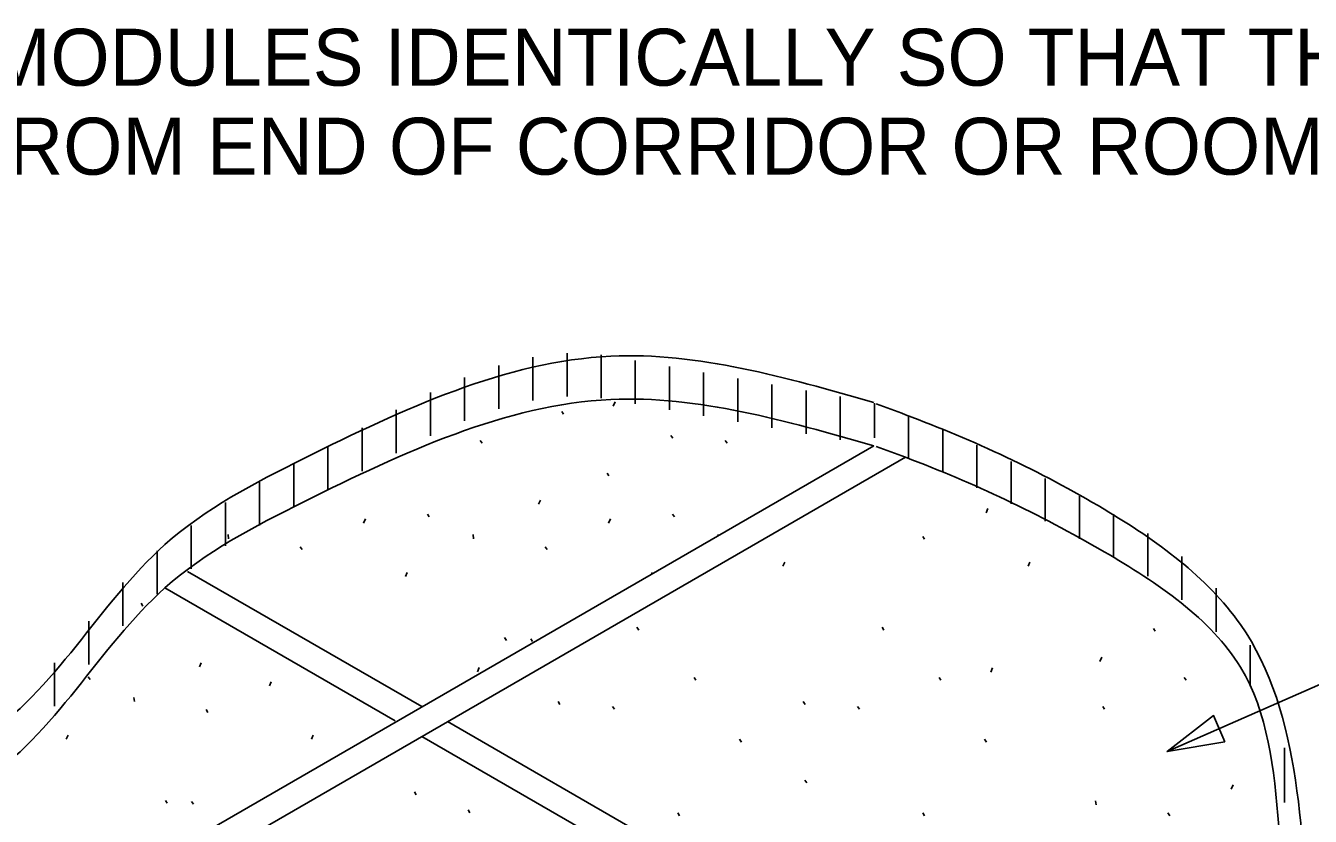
# Model space of a CAD drawing. Extents: x -12092.5 to -12048.3, y -12283.2 to -12205.8.
# Drawn here: x -12075.14 to -12060.1, y -12253.65 to -12244.4 of the extents above; entities that cross this region are included whole.
import ezdxf

# ---------------------------------------------------------------- set-up
doc = ezdxf.new("R2010")
doc.units = 0
for name, color, linetype in [('G-ANNO-TEXT', 7, 'Continuous'), ('G-DETL-LINE', 7, 'Continuous'), ('G-DETL-PATT', 7, 'Continuous')]:
    doc.layers.add(name, color=color, linetype=linetype)

msp = doc.modelspace()

# ---------------------------------------------------------------- linework, layer by layer
at = {"layer": 'G-ANNO-TEXT'}
msp.add_line((-12056.825041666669, -12250.714299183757), (-12061.776083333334, -12252.892184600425), dxfattribs=at)
msp.add_lwpolyline([(-12061.098739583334, -12252.776312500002), (-12061.776083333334, -12252.892187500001), (-12061.232958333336, -12252.471197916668)], close=True, dxfattribs=at)
at = {"layer": 'G-DETL-LINE'}
for p, q in [((-12065.209760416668, -12249.312927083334), (-12087.406947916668, -12262.1285)), ((-12064.841333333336, -12249.446656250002), (-12087.432489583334, -12262.489625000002)), ((-12073.246770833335, -12250.782447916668), (-12070.504281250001, -12252.365822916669)), ((-12070.813479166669, -12252.533729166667), (-12073.510177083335, -12250.976802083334)), ((-12070.200906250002, -12252.541000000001), (-12062.680635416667, -12256.882791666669)), ((-12062.980645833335, -12257.056000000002), (-12070.500906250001, -12252.714197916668))]:
    msp.add_line(p, q, dxfattribs=at)
for points in [[(-12065.209760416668, -12248.805854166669), (-12068.289083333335, -12248.263375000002), (-12071.882447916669, -12249.459791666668), (-12073.510843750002, -12250.469312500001), (-12075.660083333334, -12252.742270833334), (-12078.577770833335, -12254.06140625), (-12080.241072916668, -12256.115031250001), (-12082.416833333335, -12256.791677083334), (-12085.365218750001, -12258.540291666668), (-12087.392239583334, -12261.546677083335), (-12087.416020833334, -12262.222104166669)], [(-12065.209760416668, -12249.312927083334), (-12068.289083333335, -12248.770458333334), (-12071.882447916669, -12249.966864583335), (-12073.510843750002, -12250.976395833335), (-12075.660083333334, -12253.249343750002), (-12078.577770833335, -12254.568479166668), (-12080.241072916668, -12256.622104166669), (-12082.416833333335, -12257.298750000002), (-12085.365218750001, -12259.047364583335), (-12087.392239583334, -12262.053750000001), (-12087.392239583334, -12263.004739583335), (-12085.887333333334, -12270.45934375), (-12085.273083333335, -12271.195604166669), (-12082.387489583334, -12274.137000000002), (-12077.473510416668, -12274.658520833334), (-12076.367854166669, -12274.658520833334), (-12074.064416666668, -12273.584802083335), (-12070.747468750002, -12271.314677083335), (-12067.092677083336, -12270.27165625), (-12063.192208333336, -12269.382020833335), (-12061.824302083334, -12266.020250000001), (-12056.450385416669, -12263.782125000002), (-12054.537635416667, -12261.234708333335), (-12060.101572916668, -12255.740187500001), (-12060.917697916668, -12251.902302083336), (-12062.514739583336, -12250.552489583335), (-12064.841333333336, -12249.446656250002), (-12065.182322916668, -12249.321343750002)], [(-12060.101218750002, -12255.246270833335), (-12060.101572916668, -12255.24159375), (-12060.917697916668, -12251.403708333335), (-12062.514739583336, -12250.053895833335), (-12064.841333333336, -12248.948052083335), (-12065.182322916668, -12248.822739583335)]]:
    msp.add_spline(points, degree=3, dxfattribs=at)
at = {"layer": 'G-DETL-PATT'}
for p, q in [((-12069.202864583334, -12248.781031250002), (-12069.202864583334, -12248.273958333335)), ((-12068.802864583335, -12248.736291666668), (-12068.802864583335, -12248.229218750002)), ((-12068.402864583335, -12248.753270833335), (-12068.402864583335, -12248.2461875)), ((-12068.002864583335, -12248.820875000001), (-12068.002864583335, -12248.313802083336)), ((-12069.602864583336, -12248.879083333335), (-12069.602864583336, -12248.372000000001)), ((-12067.602864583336, -12248.891343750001), (-12067.602864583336, -12248.384270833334)), ((-12067.202864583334, -12248.961802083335), (-12067.202864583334, -12248.454729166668)), ((-12070.002864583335, -12249.021187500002), (-12070.002864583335, -12248.514114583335)), ((-12066.802864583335, -12249.032281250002), (-12066.802864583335, -12248.525208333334)), ((-12066.402864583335, -12249.102739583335), (-12066.402864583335, -12248.595666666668)), ((-12070.402864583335, -12249.197427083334), (-12070.402864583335, -12248.690354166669)), ((-12066.002864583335, -12249.173208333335), (-12066.002864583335, -12248.666125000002)), ((-12065.602864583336, -12249.243677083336), (-12065.602864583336, -12248.736604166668)), ((-12070.802864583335, -12249.397250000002), (-12070.802864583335, -12248.890177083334)), ((-12068.865145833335, -12248.909625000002), (-12068.843583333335, -12248.941989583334)), ((-12068.261354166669, -12248.846593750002), (-12068.239760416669, -12248.798031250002)), ((-12065.202864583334, -12249.22071875), (-12065.202864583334, -12248.815354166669)), ((-12064.802864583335, -12249.461541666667), (-12064.802864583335, -12248.962937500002)), ((-12071.202864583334, -12249.609614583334), (-12071.202864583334, -12249.102541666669)), ((-12067.586989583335, -12249.191812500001), (-12067.565427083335, -12249.224218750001)), ((-12064.402864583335, -12249.625041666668), (-12064.402864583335, -12249.126437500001)), ((-12071.602864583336, -12249.823114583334), (-12071.602864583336, -12249.316041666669)), ((-12069.819260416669, -12249.250208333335), (-12069.79765625, -12249.282604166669)), ((-12066.949458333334, -12249.250208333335), (-12066.927854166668, -12249.282604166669)), ((-12064.002864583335, -12249.803104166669), (-12064.002864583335, -12249.304500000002)), ((-12063.602864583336, -12249.993531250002), (-12063.602864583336, -12249.494927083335)), ((-12072.002864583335, -12250.027989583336), (-12072.002864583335, -12249.520916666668)), ((-12068.333020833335, -12249.633343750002), (-12068.311416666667, -12249.665708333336)), ((-12072.402864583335, -12250.244583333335), (-12072.402864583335, -12249.737500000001)), ((-12063.202864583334, -12250.19371875), (-12063.202864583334, -12249.695114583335)), ((-12069.135260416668, -12249.995625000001), (-12069.113697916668, -12249.947104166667)), ((-12062.802864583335, -12250.400791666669), (-12062.802864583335, -12249.902187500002)), ((-12072.802864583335, -12250.484687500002), (-12072.802864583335, -12249.977614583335)), ((-12070.436541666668, -12250.112291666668), (-12070.414979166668, -12250.144687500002)), ((-12067.566739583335, -12250.112291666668), (-12067.545177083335, -12250.144687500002)), ((-12063.895531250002, -12250.096000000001), (-12063.873927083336, -12250.047479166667)), ((-12062.402864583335, -12250.612093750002), (-12062.402864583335, -12250.113343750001)), ((-12073.202864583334, -12250.751437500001), (-12073.202864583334, -12250.244364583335)), ((-12071.185083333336, -12250.216843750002), (-12071.163479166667, -12250.168312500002)), ((-12068.315281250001, -12250.216843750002), (-12068.293677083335, -12250.168312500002)), ((-12072.772270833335, -12250.352333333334), (-12072.766864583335, -12250.400895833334)), ((-12069.902468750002, -12250.352333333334), (-12069.897072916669, -12250.400895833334)), ((-12067.032666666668, -12250.352333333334), (-12067.031302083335, -12250.364604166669)), ((-12064.636979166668, -12250.37459375), (-12064.615416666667, -12250.406958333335)), ((-12062.002864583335, -12250.839770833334), (-12062.002864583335, -12250.338281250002)), ((-12073.602864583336, -12251.048687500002), (-12073.602864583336, -12250.541614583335)), ((-12071.926531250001, -12250.495427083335), (-12071.904968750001, -12250.52779166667)), ((-12069.056729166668, -12250.495427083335), (-12069.035166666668, -12250.52779166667)), ((-12066.274385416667, -12250.721802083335), (-12066.252781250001, -12250.673239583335)), ((-12063.404583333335, -12250.721802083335), (-12063.382979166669, -12250.673239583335)), ((-12061.602864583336, -12251.114520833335), (-12061.602864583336, -12250.607687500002)), ((-12070.694135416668, -12250.842645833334), (-12070.672531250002, -12250.794083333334)), ((-12067.812239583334, -12250.815479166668), (-12067.802729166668, -12250.794083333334)), ((-12074.002864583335, -12251.420250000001), (-12074.002864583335, -12250.913177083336)), ((-12061.202864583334, -12251.491541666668), (-12061.202864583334, -12250.979989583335)), ((-12073.790979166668, -12251.155343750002), (-12073.769385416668, -12251.187739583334)), ((-12074.402864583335, -12251.872427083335), (-12074.402864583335, -12251.365354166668)), ((-12067.984302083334, -12251.437125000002), (-12067.962708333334, -12251.46953125)), ((-12065.114510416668, -12251.437125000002), (-12065.092906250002, -12251.46953125)), ((-12061.937468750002, -12251.449468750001), (-12061.915906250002, -12251.481833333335)), ((-12069.534260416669, -12251.557968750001), (-12069.51265625, -12251.590364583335)), ((-12069.227020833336, -12251.570302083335), (-12069.205458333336, -12251.602666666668)), ((-12060.802864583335, -12252.12579166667), (-12060.802864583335, -12251.644552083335)), ((-12074.802864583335, -12252.361083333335), (-12074.802864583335, -12251.854000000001)), ((-12073.106979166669, -12251.900770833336), (-12073.085416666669, -12251.852239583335)), ((-12069.852593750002, -12251.957906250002), (-12069.830989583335, -12251.909302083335)), ((-12063.841604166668, -12251.961114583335), (-12063.820010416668, -12251.912552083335)), ((-12062.563041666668, -12251.8370625), (-12062.541447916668, -12251.78846875)), ((-12074.408270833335, -12252.017427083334), (-12074.386708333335, -12252.049833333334)), ((-12072.287010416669, -12252.121979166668), (-12072.265406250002, -12252.073458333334)), ((-12067.315197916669, -12252.024156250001), (-12067.293635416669, -12252.056520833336)), ((-12064.445395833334, -12252.024156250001), (-12064.423833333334, -12252.056520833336)), ((-12061.575593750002, -12252.024156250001), (-12061.554031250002, -12252.056520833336)), ((-12073.874197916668, -12252.257468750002), (-12073.868791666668, -12252.306031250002)), ((-12068.906843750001, -12252.306343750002), (-12068.88528125, -12252.338739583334)), ((-12068.269302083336, -12252.364729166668), (-12068.247708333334, -12252.397125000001)), ((-12066.037041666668, -12252.306343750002), (-12066.015479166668, -12252.338739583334)), ((-12065.399510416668, -12252.364729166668), (-12065.377906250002, -12252.397125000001)), ((-12062.529708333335, -12252.364729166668), (-12062.508104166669, -12252.397125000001)), ((-12073.028458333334, -12252.4005625), (-12073.006895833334, -12252.432927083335)), ((-12074.665854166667, -12252.747781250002), (-12074.644260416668, -12252.699218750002)), ((-12071.796052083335, -12252.747781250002), (-12071.774458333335, -12252.699218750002)), ((-12066.783072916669, -12252.747864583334), (-12066.76146875, -12252.780229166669)), ((-12063.913270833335, -12252.747864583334), (-12063.891666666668, -12252.780229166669)), ((-12060.402864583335, -12253.487656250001), (-12060.402864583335, -12252.847593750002)), ((-12060.402864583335, -12253.401656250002), (-12060.402864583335, -12252.847593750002)), ((-12066.016791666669, -12253.226812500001), (-12065.995229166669, -12253.259218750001)), ((-12070.59028125, -12253.363656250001), (-12070.56871875, -12253.396020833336)), ((-12061.025729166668, -12253.331364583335), (-12061.004135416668, -12253.282843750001)), ((-12073.505979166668, -12253.463104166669), (-12073.484385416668, -12253.4955)), ((-12073.198739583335, -12253.475437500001), (-12073.177177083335, -12253.507802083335)), ((-12069.960604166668, -12253.575385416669), (-12069.939041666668, -12253.607750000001)), ((-12062.612916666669, -12253.466854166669), (-12062.607520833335, -12253.515416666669)), ((-12067.506781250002, -12253.609958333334), (-12067.485218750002, -12253.642312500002)), ((-12064.636979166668, -12253.609958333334), (-12064.615416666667, -12253.642312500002)), ((-12061.767177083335, -12253.609958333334), (-12061.745614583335, -12253.642312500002))]:
    msp.add_line(p, q, dxfattribs=at)

# ---------------------------------------------------------------- texts
at = {"layer": 'G-ANNO-TEXT'}
for s, p in [('LOCATE REMOTE TEST/MONITOR MODULES IDENTICALLY SO THAT THEY FORM', (-12090.452958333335, -12245.097218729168)), ('A STRAIGHT LINE WHEN VIEWED FROM END OF CORRIDOR OR ROOM.', (-12090.452958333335, -12246.138885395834))]:
    msp.add_text(s, height=0.6666666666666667, dxfattribs=at).set_placement(p)

doc.saveas('drawing.dxf')
